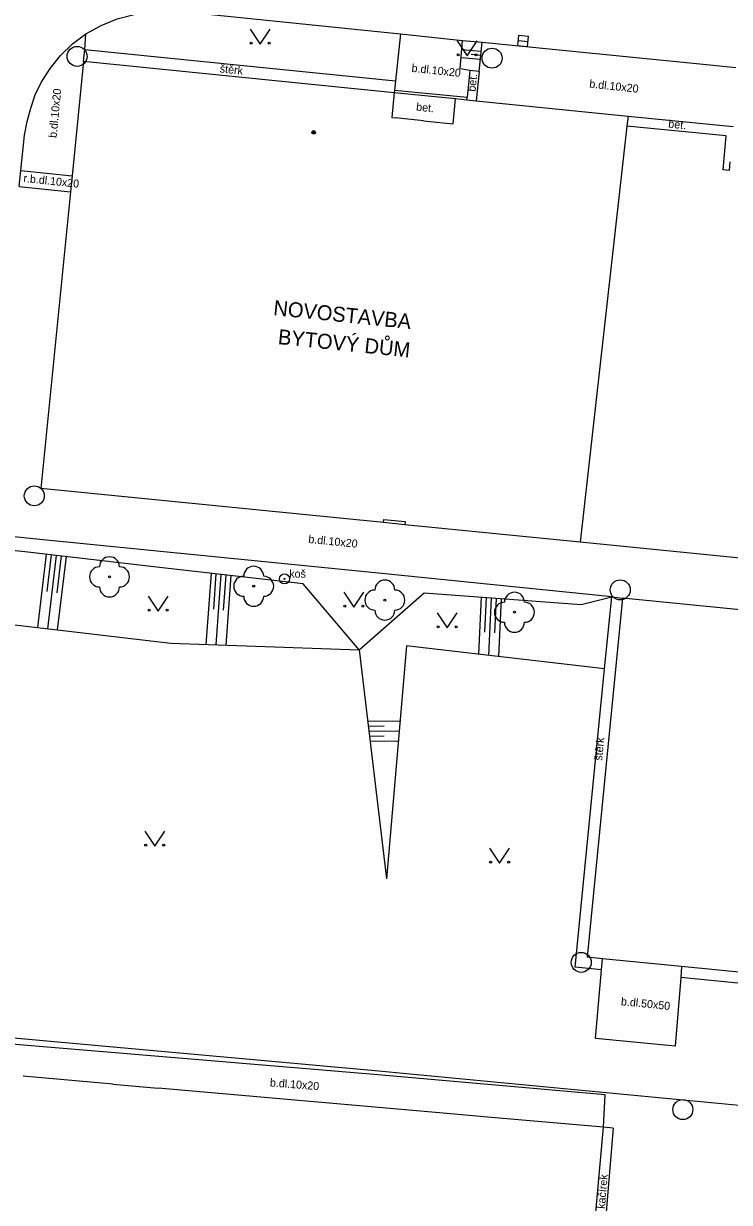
# Model space of a CAD drawing. Extents: x -598233 to -596890, y -1157848 to -1156431.
# Drawn here: x -597943.1 to -597907.8, y -1156924.2 to -1156865.2 of the extents above; entities that cross this region are included whole.
import ezdxf

# ---------------------------------------------------------------- set-up
doc = ezdxf.new("R2010")
doc.units = 0
for name, color, linetype in [('Level 10', 7, 'Continuous'), ('Level 11', 7, 'Continuous'), ('Level 14', 7, 'Continuous'), ('Level 15', 7, 'Continuous'), ('Level 22', 7, 'Continuous'), ('Level 24', 7, 'Continuous'), ('Level 25', 7, 'Continuous'), ('Level 27', 7, 'Continuous'), ('Level 36', 7, 'Continuous'), ('Level 39', 7, 'Continuous'), ('Level 40', 7, 'Continuous'), ('Level 41', 7, 'Continuous'), ('Level 42', 7, 'Continuous'), ('Level 5', 7, 'Continuous'), ('Level 6', 7, 'Continuous'), ('Level 7', 7, 'Continuous')]:
    doc.layers.add(name, color=color, linetype=linetype)

msp = doc.modelspace()

# ---------------------------------------------------------------- linework, layer by layer
at = {"layer": 'Level 10'}
for points in [[(-597939.98, -1156865.76), (-597939.21, -1156865.34), (-597938.4, -1156865.01), (-597937.56, -1156864.78), (-597936.7, -1156864.64)], [(-597935.17, -1156864.64), (-597925.22, -1156865.65)], [(-597925.22, -1156865.65), (-597924.24, -1156865.75)], [(-597942.21, -1156868.18), (-597941.76, -1156867.48), (-597941.24, -1156866.84), (-597940.64, -1156866.26), (-597939.98, -1156865.76)], [(-597924.24, -1156865.75), (-597921.14, -1156866.08)], [(-597921.14, -1156866.08), (-597920.16, -1156866.17)], [(-597920.16, -1156866.17), (-597908.94, -1156867.29)], [(-597908.94, -1156867.29), (-597907.47, -1156867.44)], [(-597943.04, -1156870.82), (-597942.91, -1156870.14), (-597942.73, -1156869.47), (-597942.5, -1156868.81), (-597942.21, -1156868.18)], [(-597943.31, -1156873.39), (-597943.23, -1156872.59), (-597943.04, -1156870.82)]]:
    msp.add_lwpolyline(points, dxfattribs=at)
at = {"layer": 'Level 11'}
for points in [[(-597940.02, -1156866.54), (-597939.98, -1156865.76)], [(-597924.24, -1156865.75), (-597924.49, -1156868.1), (-597924.54, -1156868.58)], [(-597921.25, -1156867.51), (-597921.14, -1156866.08)], [(-597920.3, -1156867.64), (-597920.16, -1156866.17)], [(-597940.09, -1156867.12), (-597940.02, -1156866.54)], [(-597940.02, -1156866.54), (-597924.49, -1156868.1)], [(-597920.3, -1156867.64), (-597920.77, -1156867.58), (-597921.25, -1156867.51)], [(-597920.77, -1156867.58), (-597920.91, -1156868.94)], [(-597920.3, -1156867.64), (-597920.45, -1156869.1)], [(-597924.54, -1156868.58), (-597924.55, -1156868.68)], [(-597943.23, -1156872.59), (-597940.66, -1156872.85)], [(-597943.31, -1156873.39), (-597940.74, -1156873.65)], [(-597942.44, -1156891.01), (-597945.02, -1156890.74)], [(-597925.33, -1156892.72), (-597942.44, -1156891.01)], [(-597913.67, -1156893.89), (-597925.33, -1156892.72)], [(-597914.03, -1156897.5), (-597913.67, -1156893.89)], [(-597913.67, -1156893.89), (-597913.14, -1156893.97)], [(-597915.51, -1156912.41), (-597914.03, -1156897.5)], [(-597914.48, -1156915.97), (-597914.19, -1156912.54), (-597914.14, -1156911.99)], [(-597914.19, -1156912.54), (-597915.51, -1156912.41)], [(-597910.18, -1156912.38), (-597910.22, -1156912.93), (-597910.5, -1156916.36)], [(-597906.71, -1156913.27), (-597910.22, -1156912.93)], [(-597925.55, -1156917.78), (-597945.3, -1156916.12)], [(-597910.5, -1156916.36), (-597914.48, -1156915.97)], [(-597914, -1156918.8), (-597925.55, -1156917.78)], [(-597914.09, -1156920.41), (-597914, -1156918.8)], [(-597913.61, -1156920.46), (-597914.09, -1156920.41)], [(-597913.61, -1156920.46), (-597913.97, -1156924.84)]]:
    msp.add_lwpolyline(points, dxfattribs=at)
at = {"layer": 'Level 14'}
for points in [[(-597942.87, -1156891.66), (-597945.67, -1156891.36)], [(-597936.58, -1156892.4), (-597942.87, -1156891.66)], [(-597929.1, -1156893.24), (-597936.58, -1156892.4)], [(-597926.31, -1156896.54), (-597929.1, -1156893.24)], [(-597926.31, -1156896.54), (-597923.06, -1156893.69)], [(-597923.06, -1156893.69), (-597915.21, -1156894.28)], [(-597915.21, -1156894.28), (-597913.67, -1156893.89)], [(-597947.37, -1156894.84), (-597935.72, -1156896.22)], [(-597935.72, -1156896.22), (-597926.31, -1156896.54)], [(-597923.94, -1156896.35), (-597924.93, -1156907.99)], [(-597914.03, -1156897.5), (-597923.39, -1156896.41), (-597923.94, -1156896.35)], [(-597926.31, -1156896.54), (-597924.93, -1156907.99)]]:
    msp.add_lwpolyline(points, dxfattribs=at)
at = {"layer": 'Level 15'}
for points in [[(-597920.2, -1156866.63), (-597921.18, -1156866.55)], [(-597920.22, -1156866.83), (-597920.71, -1156866.79)], [(-597920.24, -1156867.03), (-597921.21, -1156866.95)], [(-597941.96, -1156891.77), (-597942.39, -1156895.43)], [(-597941.71, -1156891.8), (-597941.93, -1156893.63)], [(-597941.46, -1156891.83), (-597941.89, -1156895.49)], [(-597941.21, -1156891.85), (-597941.43, -1156893.69)], [(-597940.96, -1156891.88), (-597941.4, -1156895.55)], [(-597933.71, -1156892.72), (-597933.97, -1156896.28)], [(-597933.47, -1156892.75), (-597933.59, -1156894.52)], [(-597933.22, -1156892.78), (-597933.47, -1156896.3)], [(-597932.97, -1156892.81), (-597933.1, -1156894.56)], [(-597932.72, -1156892.83), (-597932.97, -1156896.31)], [(-597920.21, -1156893.9), (-597920.34, -1156896.77)], [(-597919.96, -1156893.92), (-597920.04, -1156895.67)], [(-597919.71, -1156893.94), (-597919.84, -1156896.83)], [(-597919.46, -1156893.96), (-597919.54, -1156895.69)], [(-597919.21, -1156893.98), (-597919.34, -1156896.88)], [(-597925.88, -1156900.12), (-597924.26, -1156900.09)], [(-597925.85, -1156900.37), (-597925.06, -1156900.35)], [(-597925.82, -1156900.62), (-597924.3, -1156900.59)], [(-597925.79, -1156900.87), (-597925.06, -1156900.85)], [(-597925.76, -1156901.12), (-597924.34, -1156901.09)]]:
    msp.add_lwpolyline(points, dxfattribs=at)
at = {"layer": 'Level 22'}
for centre in [(-597938.79, -1156892.9), (-597931.58, -1156893.37), (-597925.02, -1156894.06), (-597918.54, -1156894.67)]:
    msp.add_circle(centre, 0.05, dxfattribs=at)
for centre, start, end in [((-597938.79, -1156892.4), 0, 180), ((-597939.29, -1156892.9), 90, 270), ((-597938.29, -1156892.9), 270, 90), ((-597931.58, -1156892.87), 0, 180), ((-597938.79, -1156893.4), 180, 0), ((-597932.08, -1156893.37), 90, 270), ((-597931.08, -1156893.37), 270, 90), ((-597925.02, -1156893.56), 0, 180), ((-597931.58, -1156893.87), 180, 0), ((-597925.52, -1156894.06), 90, 270), ((-597924.52, -1156894.06), 270, 90), ((-597918.54, -1156894.17), 0, 180), ((-597925.02, -1156894.56), 180, 0), ((-597919.04, -1156894.67), 90, 270), ((-597918.04, -1156894.67), 270, 90), ((-597918.54, -1156895.17), 180, 0)]:
    msp.add_arc(centre, 0.5, start, end, dxfattribs=at)
at = {"layer": 'Level 24'}
for points in [[(-597920.91, -1156868.94), (-597924.54, -1156868.58)], [(-597920.92, -1156869.05), (-597920.91, -1156868.94)]]:
    msp.add_lwpolyline(points, dxfattribs=at)
at = {"layer": 'Level 25'}
for radius in [0.25, 0.0303]:
    msp.add_circle((-597930.04, -1156893), radius, dxfattribs=at)
at = {"layer": 'Level 27'}
msp.add_line((-597918.3588, -1156866.0852), (-597917.8612, -1156866.1348), dxfattribs=at)
msp.add_lwpolyline([(-597918.3836, -1156866.3339), (-597917.8861, -1156866.3836), (-597917.8364, -1156865.8861), (-597918.3339, -1156865.8364)], close=True, dxfattribs=at)
for centre in [(-597940.41, -1156866.88), (-597919.66, -1156866.97), (-597942.55, -1156888.85), (-597913.25, -1156893.55), (-597915.2, -1156912.17), (-597910.12, -1156919.53)]:
    msp.add_circle(centre, 0.5, dxfattribs=at)
at = {"layer": 'Level 36'}
for points in [[(-597931.75, -1156865.52), (-597931.25, -1156866.27), (-597930.75, -1156865.52)], [(-597921.41, -1156866.1), (-597920.91, -1156866.85), (-597920.41, -1156866.1)], [(-597936.86, -1156893.87), (-597936.36, -1156894.62), (-597935.86, -1156893.87)], [(-597927.07, -1156893.66), (-597926.57, -1156894.41), (-597926.07, -1156893.66)], [(-597922.4, -1156894.7), (-597921.9, -1156895.45), (-597921.4, -1156894.7)], [(-597937.03, -1156905.61), (-597936.53, -1156906.36), (-597936.03, -1156905.61)], [(-597919.78, -1156906.46), (-597919.28, -1156907.21), (-597918.78, -1156906.46)]]:
    msp.add_lwpolyline(points, dxfattribs=at)
for centre in [(-597931.7002, -1156866.2198), (-597930.8008, -1156866.2198), (-597921.3602, -1156866.7998), (-597920.4608, -1156866.7998), (-597936.8102, -1156894.5698), (-597935.9108, -1156894.5698), (-597927.0202, -1156894.3598), (-597926.1208, -1156894.3598), (-597922.3502, -1156895.3998), (-597921.4508, -1156895.3998), (-597936.9802, -1156906.3098), (-597936.0808, -1156906.3098), (-597919.7302, -1156907.1598), (-597918.8308, -1156907.1598)]:
    msp.add_circle(centre, 0.05, dxfattribs=at)
at = {"layer": 'Level 39'}
for radius in [0.09, 0.0398]:
    msp.add_circle((-597928.58, -1156870.68), radius, dxfattribs=at)
at = {"layer": 'Level 5'}
for points in [[(-597940.09, -1156867.12), (-597940.66, -1156872.85), (-597940.74, -1156873.65), (-597942.23, -1156888.48)], [(-597940.09, -1156867.12), (-597924.55, -1156868.68), (-597921.49, -1156868.99), (-597920.92, -1156869.05), (-597920.45, -1156869.1), (-597912.86, -1156869.87)], [(-597924.55, -1156868.68), (-597924.67, -1156869.94)], [(-597921.61, -1156870.25), (-597921.49, -1156868.99)], [(-597924.67, -1156869.94), (-597924.48, -1156869.96)], [(-597923.08, -1156870.1), (-597924.48, -1156869.96)], [(-597923.08, -1156870.1), (-597921.61, -1156870.25)], [(-597912.86, -1156869.87), (-597912.92, -1156870.37), (-597915.25, -1156891.17)], [(-597847.98, -1156897.89), (-597850.55, -1156897.64), (-597850.83, -1156897.61), (-597852.21, -1156897.47), (-597852.62, -1156897.43), (-597867.77, -1156895.92), (-597872.23, -1156895.47), (-597872.78, -1156895.41), (-597872.8, -1156895.41), (-597878.73, -1156894.82), (-597878.76, -1156894.82), (-597896.73, -1156893.02), (-597898, -1156892.89), (-597899.04, -1156892.79), (-597900.92, -1156892.6), (-597915.25, -1156891.17), (-597924.02, -1156890.3), (-597925.08, -1156890.19), (-597942.23, -1156888.48)], [(-597925.08, -1156890.19), (-597925.07, -1156890.04)], [(-597925.07, -1156890.04), (-597924.01, -1156890.14)], [(-597924.01, -1156890.14), (-597924.02, -1156890.3)], [(-597913.14, -1156893.97), (-597914.91, -1156911.91)], [(-597888.91, -1156896.36), (-597896.99, -1156895.56), (-597897.52, -1156895.51), (-597900.69, -1156895.2), (-597901.18, -1156895.15), (-597913.14, -1156893.97)], [(-597888.91, -1156896.36), (-597888.93, -1156896.53), (-597888.94, -1156896.68), (-597890.69, -1156914.3), (-597891.47, -1156914.22), (-597895.45, -1156913.83), (-597898.95, -1156913.49), (-597899.42, -1156913.44), (-597903.4, -1156913.05), (-597906.66, -1156912.73), (-597910.18, -1156912.38), (-597914.14, -1156911.99), (-597914.91, -1156911.91)], [(-597938.62, -1156918.26), (-597943.1, -1156917.86)], [(-597938.62, -1156918.26), (-597936.35, -1156918.46)], [(-597922.1, -1156919.71), (-597936.35, -1156918.46)], [(-597919.88, -1156919.91), (-597922.1, -1156919.71)], [(-597914.09, -1156920.41), (-597919.88, -1156919.91)], [(-597915.26, -1156933.36), (-597914.09, -1156920.41)]]:
    msp.add_lwpolyline(points, dxfattribs=at)
at = {"layer": 'Level 6'}
for points in [[(-597938.62, -1156918.26), (-597936.35, -1156918.46)], [(-597919.88, -1156919.91), (-597922.1, -1156919.71)]]:
    msp.add_lwpolyline(points, dxfattribs=at)
at = {"layer": 'Level 7'}
for points in [[(-597907.95, -1156870.85), (-597912.92, -1156870.37)], [(-597912.86, -1156869.87), (-597907.6, -1156870.38)], [(-597908.11, -1156872.55), (-597907.95, -1156870.85)], [(-597907.77, -1156872.16), (-597907.81, -1156872.58)], [(-597907.81, -1156872.58), (-597908.11, -1156872.55)], [(-597945.26, -1156915.79), (-597925.5, -1156917.57), (-597907.31, -1156919.31)]]:
    msp.add_lwpolyline(points, dxfattribs=at)

# ---------------------------------------------------------------- texts
at = {"layer": 'Level 40'}
for s, height, rotation, p in [('štěrk', 0.4, 354.256489, (-597933.29, -1156867.68)), ('b.dl.10x20', 0.4, 353.923653, (-597923.7, -1156867.65)), ('bet.', 0.4, 84.241739, (-597920.49, -1156868.66)), ('b.dl.10x20', 0.4, 353.923653, (-597914.81, -1156868.44)), ('b.dl.10x20', 0.4, 84.3381, (-597941.44, -1156870.97)), ('bet.', 0.4, 354.215261, (-597923.47, -1156869.59)), ('bet.', 0.4, 354.472461, (-597910.86, -1156870.44)), ('r.b.dl.10x20', 0.400002, 354, (-597943.11, -1156873.16)), ('b.dl.10x20', 0.4, 354.269547, (-597928.86, -1156891.2)), ('štěrk', 0.4, 84.305208, (-597914.16, -1156902.1)), ('b.dl.50x50', 0.4, 354.269547, (-597913.23, -1156914.31)), ('b.dl.10x20', 0.4, 355.569222, (-597930.78, -1156918.37)), ('kačírek', 0.4, 85.066149, (-597914.02, -1156924.5))]:
    msp.add_text(s, height=height, rotation=rotation, dxfattribs=at).set_placement(p)
at = {"layer": 'Level 41'}
for s, rotation, p in [('NOVOSTAVBA', 354.163856, (-597930.62, -1156879.81)), ('BYTOVÝ DŮM', 354.161825, (-597930.39, -1156881.26))]:
    msp.add_text(s, height=0.75, rotation=rotation, dxfattribs=at).set_placement(p)
at = {"layer": 'Level 42'}
msp.add_text('koš', height=0.4, dxfattribs=at).set_placement((-597929.8, -1156892.94))

doc.saveas('drawing.dxf')
